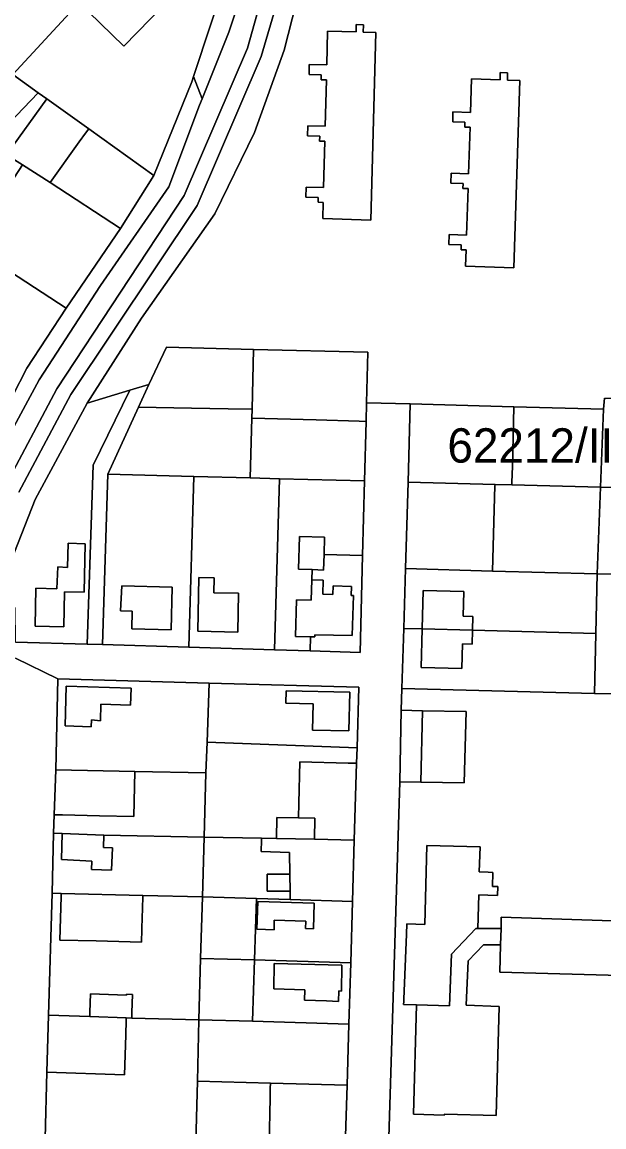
# Model space of a CAD drawing. Extents: x -502026 to -497664, y -1143484 to -1138019.
# Drawn here: x -498053.3 to -497917.6, y -1140189 to -1139931.4 of the extents above; entities that cross this region are included whole.
import ezdxf

# ---------------------------------------------------------------- set-up
doc = ezdxf.new("R2010")
doc.units = 0
for name, color, linetype in [('25', 7, 'Continuous'), ('31', 7, 'Continuous'), ('37', 7, 'Continuous'), ('43', 7, 'Continuous'), ('49', 7, 'Continuous'), ('55', 7, 'Continuous'), ('62', 7, 'Continuous'), ('7', 7, 'Continuous')]:
    doc.layers.add(name, color=color, linetype=linetype)

msp = doc.modelspace()

# ---------------------------------------------------------------- linework, layer by layer
at = {"layer": '25'}
for points in [[(-498005.22, -1139919.56), (-498013.29, -1139944.08), (-498013.7, -1139945.33), (-498022.56, -1139967.15), (-498037.76, -1139956.26), (-498047.52, -1139949.27), (-498049.52, -1139947.83), (-498055.44, -1139943.59), (-498027.12, -1139912.89)], [(-498020.21, -1139927.43), (-498028.47, -1139919.4), (-498037.8, -1139929), (-498029.54, -1139937.02)], [(-498047.52, -1139949.27), (-498056.92, -1139962.31), (-498053.17, -1139964.63), (-498065.44, -1139983.49), (-498043.03, -1139998.07), (-498052.15, -1140012.08), (-498058.96, -1140025.11), (-498063.8, -1140022.04), (-498076.32, -1140014.11), (-498093.67, -1140016.92), (-498094.53, -1140023.68), (-498095.59, -1140032.09), (-498118.27, -1140027.6), (-498121.71, -1140026.79), (-498122.55, -1140009.45), (-498079.55, -1139968), (-498078.04, -1139969.45), (-498073.93, -1139965.16), (-498069.88, -1139969.05), (-498049.52, -1139947.83)], [(-498037.76, -1139956.26), (-498038.47, -1139957.24), (-498039.95, -1139959.31), (-498046.76, -1139968.79), (-498053.17, -1139964.63), (-498056.92, -1139962.31), (-498047.52, -1139949.27)], [(-498046.76, -1139968.79), (-498030.37, -1139979.5), (-498043.03, -1139998.07), (-498065.44, -1139983.49), (-498053.17, -1139964.63)], [(-498038.09, -1140076.42), (-498054.83, -1140075.94), (-498054.88, -1140067.92), (-498059.95, -1140067.22), (-498050.2, -1140042.69), (-498038.13, -1140020.23), (-498028.18, -1140017.21), (-498036.75, -1140034.66)], [(-497999.66, -1140021.66), (-497999.71, -1140023.69), (-498000.11, -1140037.65), (-498013.26, -1140037.31), (-498033.33, -1140036.77), (-498026.13, -1140021.13), (-498013.75, -1140021.38), (-498005.23, -1140021.55)], [(-497917.72, -1140021.63), (-497918.4, -1140039.82), (-497939.09, -1140039.26), (-497939.07, -1140038.61), (-497938.97, -1140035.01), (-497938.59, -1140021.1)], [(-497973.05, -1140024.47), (-497973.42, -1140038.36), (-497993.26, -1140037.83), (-498000.11, -1140037.65), (-497999.71, -1140023.69), (-497984.71, -1140024.11), (-497974.68, -1140024.42)], [(-498013.26, -1140037.31), (-498014.44, -1140077.12), (-498034.57, -1140076.51), (-498033.33, -1140036.77)], [(-498000.11, -1140037.65), (-497993.26, -1140037.83), (-497994.45, -1140077.73), (-498014.44, -1140077.12), (-498013.26, -1140037.31)], [(-497973.42, -1140038.36), (-497973.88, -1140055.76), (-497982.88, -1140055.52), (-497982.75, -1140051.46), (-497988.62, -1140051.29), (-497988.84, -1140058.94), (-497985.67, -1140059.04), (-497985.73, -1140061.42), (-497985.85, -1140066.15), (-497989.29, -1140066.08), (-497989.52, -1140074.6), (-497986.07, -1140074.7), (-497986.15, -1140077.99), (-497994.45, -1140077.73), (-497993.26, -1140037.83)], [(-497939.09, -1140039.26), (-497918.4, -1140039.82), (-497919.2, -1140060.05), (-497943.58, -1140059.37), (-497943.18, -1140045.02), (-497943.02, -1140039.47), (-497943.01, -1140039.15)], [(-498038.56, -1140053.03), (-498042.57, -1140052.9), (-498042.73, -1140058.52), (-498044.98, -1140058.42), (-498045.21, -1140063.52), (-498050.12, -1140063.35), (-498050.27, -1140072.23), (-498043.54, -1140072.4), (-498043.37, -1140064.23), (-498038.82, -1140064.26)], [(-497943.58, -1140059.37), (-497919.2, -1140060.05), (-497919.5, -1140073.92), (-497948.27, -1140073.16), (-497948.2, -1140069.94), (-497950.46, -1140069.88), (-497950.32, -1140064.15), (-497959.77, -1140063.92), (-497959.99, -1140072.87), (-497964.3, -1140072.76), (-497963.85, -1140058.8)], [(-498002.79, -1140064.56), (-498008.56, -1140064.44), (-498008.49, -1140060.93), (-498012.05, -1140060.86), (-498012.3, -1140073.4), (-498002.97, -1140073.59)], [(-498018.3, -1140063.13), (-498030.01, -1140062.84), (-498030.31, -1140068.62), (-498027.59, -1140068.69), (-498027.7, -1140072.86), (-498018.55, -1140073.09)], [(-497959.99, -1140072.87), (-497960.21, -1140081.82), (-497950.76, -1140082.05), (-497950.62, -1140076.32), (-497948.35, -1140076.38), (-497948.27, -1140073.16), (-497919.5, -1140073.92), (-497919.78, -1140087.89), (-497964.76, -1140086.73), (-497964.3, -1140072.76)], [(-498009.63, -1140085.48), (-498010.15, -1140099.29), (-498010.42, -1140106.45), (-498027.03, -1140106.09), (-498045.43, -1140105.7), (-498044.98, -1140084.53)], [(-497975.18, -1140100.61), (-498010.15, -1140099.29), (-498009.63, -1140085.48), (-497974.76, -1140086.42)], [(-498027.85, -1140086.66), (-498043.02, -1140086.22), (-498043.23, -1140095.48), (-498037.18, -1140095.66), (-498037.11, -1140094.08), (-498035.02, -1140094.25), (-498034.91, -1140090.41), (-498028.03, -1140090.62)], [(-497976.85, -1140087.63), (-497991.72, -1140087.29), (-497991.79, -1140090.16), (-497985.44, -1140090.31), (-497985.58, -1140096.46), (-497977.06, -1140096.65)], [(-497975.18, -1140100.61), (-497975.29, -1140104.17), (-497977.24, -1140104.12), (-497988.55, -1140103.85), (-497988.78, -1140113.5), (-497988.86, -1140116.92), (-497993.85, -1140116.82), (-497993.95, -1140121.74), (-497997.45, -1140121.67), (-498010.81, -1140121.42), (-498010.42, -1140106.45), (-498010.15, -1140099.29)], [(-498010.42, -1140106.45), (-498010.81, -1140121.42), (-498034.19, -1140120.97), (-498043.93, -1140120.58), (-498045.95, -1140120.5), (-498045.8, -1140116.2), (-498043.85, -1140116.24), (-498035.25, -1140116.42), (-498027.25, -1140116.59), (-498027.03, -1140106.09)], [(-498043.93, -1140120.58), (-498044.13, -1140126.61), (-498037.03, -1140126.98), (-498037.11, -1140128.93), (-498032.41, -1140129.12), (-498032.2, -1140123.88), (-498034.3, -1140123.8), (-498034.19, -1140120.97), (-498010.81, -1140121.42), (-498011.23, -1140135.35), (-498025.15, -1140135), (-498044.18, -1140134.53), (-498046.31, -1140134.48), (-498045.95, -1140120.5)], [(-497997.45, -1140121.67), (-497997.46, -1140122.08), (-497997.56, -1140124.78), (-497990.91, -1140125.01), (-497990.85, -1140130.04), (-497996.15, -1140130.04), (-497996.15, -1140134.03), (-497990.8, -1140134.03), (-497990.78, -1140135.96), (-497998.6, -1140135.73), (-498011.23, -1140135.35), (-498010.81, -1140121.42)], [(-498044.18, -1140134.53), (-498044.2, -1140135.23), (-498044.46, -1140145.41), (-498036.05, -1140145.62), (-498025.45, -1140145.88), (-498025.29, -1140139.96), (-498025.24, -1140138.26), (-498025.15, -1140135), (-498011.23, -1140135.35), (-498011.66, -1140149.69), (-498012.08, -1140163.99), (-498027.72, -1140163.59), (-498027.68, -1140162.27), (-498027.55, -1140158.07), (-498028.95, -1140158.03), (-498028.96, -1140158.23), (-498037.35, -1140157.96), (-498037.49, -1140162.21), (-498037.52, -1140163.26), (-498047.11, -1140162.92), (-498046.31, -1140134.48)], [(-497998.6, -1140135.73), (-497999.09, -1140150.05), (-498011.66, -1140149.69), (-498011.23, -1140135.35)], [(-497999.09, -1140150.05), (-497999.58, -1140164.34), (-498012.08, -1140163.99), (-498011.66, -1140149.69)], [(-498027.72, -1140163.59), (-498012.08, -1140163.99), (-498012.35, -1140178.27), (-498012.76, -1140192.53), (-498025.24, -1140192.2), (-498047.91, -1140191.6), (-498047.48, -1140176.22), (-498029.39, -1140176.79), (-498029.1, -1140167.6), (-498028.99, -1140164.11), (-498028.98, -1140163.56)], [(-497995.39, -1140178.74), (-497995.41, -1140179.91), (-497995.45, -1140182.15), (-497995.67, -1140193.09), (-497977.93, -1140193.45), (-497978.15, -1140207.04), (-498013.02, -1140205.86), (-498012.76, -1140192.53), (-498012.35, -1140178.27)]]:
    msp.add_lwpolyline(points, close=True, dxfattribs=at)
at = {"layer": '31'}
msp.add_lwpolyline([(-497919.78, -1140087.89), (-497914.28, -1140087.97), (-497910.2, -1140087.99), (-497909.93, -1140102.1), (-497891.84, -1140102.75), (-497886.98, -1140102.93), (-497886.6, -1140093.94), (-497883.55, -1140094.07), (-497883.98, -1140104.14), (-497844.89, -1140104.71), (-497845.87, -1140137.92), (-497847.61, -1140196.96), (-497967.82, -1140193.95), (-497965.21, -1140108.5), (-497960.29, -1140108.61), (-497950.17, -1140108.76), (-497949.77, -1140092.14), (-497959.95, -1140091.98), (-497964.86, -1140091.83), (-497964.76, -1140086.73)], close=True, dxfattribs=at)
msp.add_lwpolyline([(-497910.97, -1140141.1), (-497941.61, -1140140.04), (-497941.6, -1140142.72), (-497946.98, -1140142.7), (-497946.81, -1140134.89), (-497944.72, -1140134.94), (-497942.42, -1140134.99), (-497942.37, -1140132.9), (-497943.57, -1140132.88), (-497943.49, -1140129.63), (-497944.6, -1140129.6), (-497946.69, -1140129.53), (-497946.48, -1140123.68), (-497958.94, -1140123.36), (-497959.38, -1140141.79), (-497963.56, -1140141.61), (-497963.66, -1140143.99), (-497964.27, -1140159.22), (-497964.29, -1140159.72), (-497964.32, -1140160.43), (-497961.31, -1140160.5), (-497962.04, -1140186.01), (-497954.85, -1140186.22), (-497954.81, -1140185.98), (-497942.73, -1140186.33), (-497942.07, -1140160.88), (-497949.71, -1140160.61), (-497949.28, -1140150.25), (-497945.73, -1140146.52), (-497941.7, -1140146.55), (-497941.91, -1140152.89), (-497911.05, -1140153.78)], dxfattribs=at)
at = {"layer": '37'}
msp.add_lwpolyline([(-498027.12, -1139912.89), (-498055.44, -1139943.59), (-498049.52, -1139947.83), (-498069.88, -1139969.05), (-498073.93, -1139965.16), (-498078.04, -1139969.45), (-498079.55, -1139968), (-498122.55, -1140009.45), (-498134.19, -1139993.42), (-498132.36, -1139979.34), (-498140.96, -1139969.15), (-498140.08, -1139963.56), (-498120.51, -1139961.49), (-498112.66, -1139952.19), (-498096.58, -1139946.36), (-498093.06, -1139940.14), (-498073.7, -1139934.12), (-498075.01, -1139920.31), (-498049.57, -1139915.41), (-498034.71, -1139902.25)], close=True, dxfattribs=at)
at = {"layer": '43'}
msp.add_lwpolyline([(-498000.78, -1139920.93), (-498005.08, -1139933.72), (-498011.32, -1139949.27), (-498013.29, -1139944.08), (-498005.22, -1139919.56)], dxfattribs=at)
at = {"layer": '49'}
for points in [[(-497989.72, -1139912.63), (-497997.51, -1139939.38), (-498012.5, -1139974.16), (-498041.93, -1140018.22), (-498054.05, -1140040.95)], [(-498057.39, -1140039.9), (-498045.16, -1140016.86), (-498015.53, -1139971.77), (-498000.7, -1139937.46), (-497994.32, -1139914.64)]]:
    msp.add_lwpolyline(points, dxfattribs=at)
at = {"layer": '55'}
for points in [[(-497982.83, -1139901.29), (-497992.15, -1139937.92), (-497999.1, -1139957.15), (-498008.36, -1139976.05), (-498025.48, -1140000.43), (-498038.13, -1140020.23), (-498050.2, -1140042.69), (-498059.95, -1140067.22)], [(-498054.05, -1140040.95), (-498041.93, -1140018.22), (-498012.5, -1139974.16), (-497997.51, -1139939.38), (-497989.72, -1139912.63)], [(-497994.32, -1139914.64), (-498000.7, -1139937.46), (-498015.53, -1139971.77), (-498045.16, -1140016.86), (-498057.39, -1140039.9)], [(-498061.7, -1140037.59), (-498049.31, -1140014.76), (-498035.04, -1139992.75), (-498019.07, -1139969.8), (-498011.9, -1139950.71), (-498011.32, -1139949.27), (-498005.08, -1139933.72), (-498000.78, -1139920.93)], [(-498058.96, -1140025.11), (-498052.15, -1140012.08), (-498043.03, -1139998.07), (-498030.37, -1139979.5), (-498022.56, -1139967.15), (-498013.7, -1139945.33), (-498013.29, -1139944.08), (-498011.32, -1139949.27), (-498011.9, -1139950.71), (-498019.07, -1139969.8), (-498035.04, -1139992.75), (-498049.31, -1140014.76), (-498061.7, -1140037.59)], [(-498054.83, -1140075.94), (-498038.09, -1140076.42), (-498034.57, -1140076.51), (-498014.44, -1140077.12), (-497994.45, -1140077.73), (-497986.15, -1140077.99), (-497974.47, -1140078.35), (-497973.88, -1140055.76), (-497973.42, -1140038.36), (-497973.05, -1140024.47), (-497972.94, -1140020.12), (-497962.79, -1140020.41), (-497963.26, -1140038.61), (-497963.85, -1140058.8), (-497964.3, -1140072.76), (-497964.76, -1140086.73), (-497964.86, -1140091.83), (-497965.21, -1140108.5), (-497967.82, -1140193.95)], [(-498054.82, -1140079.71), (-498044.98, -1140084.53), (-498045.43, -1140105.7), (-498045.8, -1140116.2), (-498045.95, -1140120.5), (-498046.31, -1140134.48), (-498047.11, -1140162.92), (-498047.48, -1140176.22), (-498047.91, -1140191.6), (-498048.33, -1140205.79), (-498048.75, -1140220.07), (-498049.18, -1140234.51), (-498049.6, -1140248.54), (-498050.04, -1140263.52), (-498050.48, -1140278.43), (-498050.89, -1140292.25), (-498051.72, -1140319.34), (-498061.89, -1140318.32)], [(-497977.93, -1140193.45), (-497977.51, -1140179.27), (-497977.09, -1140164.98), (-497976.66, -1140150.68), (-497976.24, -1140136.39), (-497975.82, -1140122.09), (-497975.29, -1140104.17), (-497975.18, -1140100.61), (-497974.76, -1140086.42), (-498009.63, -1140085.48), (-498044.98, -1140084.53), (-498054.82, -1140079.71)]]:
    msp.add_lwpolyline(points, dxfattribs=at)
for points in [[(-498020.21, -1139927.43), (-498029.54, -1139937.02), (-498037.8, -1139929), (-498028.47, -1139919.4)], [(-497973.68, -1139932.01), (-497973.72, -1139933.69), (-497970.82, -1139933.82), (-497971.93, -1139977.57), (-497983.18, -1139977.2), (-497983.08, -1139973.42), (-497984.28, -1139973.39), (-497984.25, -1139972.24), (-497987.12, -1139972.16), (-497987.06, -1139969.83), (-497982.99, -1139969.93), (-497982.71, -1139959.14), (-497983.91, -1139959.11), (-497983.88, -1139957.96), (-497986.75, -1139957.88), (-497986.68, -1139955.54), (-497982.62, -1139955.65), (-497982.34, -1139944.85), (-497983.54, -1139944.82), (-497983.51, -1139943.67), (-497986.37, -1139943.6), (-497986.31, -1139941.26), (-497982.25, -1139941.37), (-497982.04, -1139933.47), (-497975.4, -1139933.64), (-497975.36, -1139931.96)], [(-497940.08, -1139943.18), (-497940.11, -1139944.91), (-497937.2, -1139945.02), (-497938.59, -1139988.67), (-497949.86, -1139988.3), (-497949.74, -1139984.51), (-497950.94, -1139984.48), (-497950.91, -1139983.33), (-497953.78, -1139983.24), (-497953.7, -1139980.89), (-497949.63, -1139981.02), (-497949.29, -1139970.21), (-497950.49, -1139970.17), (-497950.46, -1139969.02), (-497953.33, -1139968.93), (-497953.26, -1139966.59), (-497949.18, -1139966.72), (-497948.84, -1139955.91), (-497950.05, -1139955.87), (-497950.01, -1139954.72), (-497952.88, -1139954.63), (-497952.81, -1139952.29), (-497948.74, -1139952.42), (-497948.49, -1139944.6), (-497941.81, -1139944.85), (-497941.78, -1139943.15)], [(-498022.56, -1139967.15), (-498030.37, -1139979.5), (-498046.76, -1139968.79), (-498039.95, -1139959.31), (-498038.47, -1139957.24), (-498037.76, -1139956.26)], [(-497999.32, -1140007.68), (-497999.66, -1140021.66), (-498005.23, -1140021.55), (-498013.75, -1140021.38), (-498026.13, -1140021.13), (-498023.7, -1140015.86), (-498019.61, -1140007.15)], [(-497972.94, -1140020.12), (-497973.05, -1140024.47), (-497974.68, -1140024.42), (-497984.71, -1140024.11), (-497999.71, -1140023.69), (-497999.66, -1140021.66), (-497999.32, -1140007.68), (-497972.63, -1140008.37)], [(-498026.13, -1140021.13), (-498033.33, -1140036.77), (-498034.57, -1140076.51), (-498038.09, -1140076.42), (-498036.75, -1140034.66), (-498028.18, -1140017.21), (-498023.7, -1140015.86)], [(-497938.59, -1140021.1), (-497938.97, -1140035.01), (-497939.07, -1140038.61), (-497939.09, -1140039.26), (-497943.01, -1140039.15), (-497963.26, -1140038.61), (-497962.79, -1140020.41)], [(-497912.35, -1140019.09), (-497912.82, -1140025.22), (-497913.06, -1140039.93), (-497918.4, -1140039.82), (-497917.72, -1140021.63), (-497917.52, -1140019.03)], [(-497943.01, -1140039.15), (-497943.02, -1140039.47), (-497943.18, -1140045.02), (-497943.58, -1140059.37), (-497963.85, -1140058.8), (-497963.26, -1140038.61)], [(-497913.06, -1140039.93), (-497913.49, -1140060.12), (-497919.2, -1140060.05), (-497918.4, -1140039.82)], [(-497982.88, -1140055.52), (-497983, -1140059.13), (-497985.67, -1140059.04), (-497988.84, -1140058.94), (-497988.62, -1140051.29), (-497982.75, -1140051.46)], [(-498038.56, -1140053.03), (-498038.82, -1140064.26), (-498043.37, -1140064.23), (-498043.54, -1140072.4), (-498050.27, -1140072.23), (-498050.12, -1140063.35), (-498045.21, -1140063.52), (-498044.98, -1140058.42), (-498042.73, -1140058.52), (-498042.57, -1140052.9)], [(-497973.88, -1140055.76), (-497974.47, -1140078.35), (-497986.15, -1140077.99), (-497986.07, -1140074.7), (-497985.02, -1140074.73), (-497985.01, -1140074.22), (-497976.35, -1140074.4), (-497975.98, -1140065.03), (-497976.56, -1140065.03), (-497976.46, -1140062.97), (-497980.76, -1140062.84), (-497980.82, -1140064.86), (-497983.14, -1140064.77), (-497983.06, -1140061.5), (-497985.73, -1140061.42), (-497985.67, -1140059.04), (-497983, -1140059.13), (-497982.88, -1140055.52)], [(-498002.79, -1140064.56), (-498002.97, -1140073.59), (-498012.3, -1140073.4), (-498012.05, -1140060.86), (-498008.49, -1140060.93), (-498008.56, -1140064.44)], [(-497986.07, -1140074.7), (-497989.52, -1140074.6), (-497989.29, -1140066.08), (-497985.85, -1140066.15), (-497985.73, -1140061.42), (-497983.06, -1140061.5), (-497983.14, -1140064.77), (-497980.82, -1140064.86), (-497980.76, -1140062.84), (-497976.46, -1140062.97), (-497976.56, -1140065.03), (-497975.98, -1140065.03), (-497976.35, -1140074.4), (-497985.01, -1140074.22), (-497985.02, -1140074.73)], [(-497913.49, -1140060.12), (-497913.85, -1140073.22), (-497913.87, -1140074), (-497914.23, -1140086.21), (-497914.28, -1140087.97), (-497919.78, -1140087.89), (-497919.5, -1140073.92), (-497919.2, -1140060.05)], [(-498018.3, -1140063.13), (-498018.55, -1140073.09), (-498027.7, -1140072.86), (-498027.59, -1140068.69), (-498030.31, -1140068.62), (-498030.01, -1140062.84)], [(-497948.27, -1140073.16), (-497959.99, -1140072.87), (-497959.77, -1140063.92), (-497950.32, -1140064.15), (-497950.46, -1140069.88), (-497948.2, -1140069.94)], [(-497948.27, -1140073.16), (-497948.35, -1140076.38), (-497950.62, -1140076.32), (-497950.76, -1140082.05), (-497960.21, -1140081.82), (-497959.99, -1140072.87)], [(-498027.85, -1140086.66), (-498028.03, -1140090.62), (-498034.91, -1140090.41), (-498035.02, -1140094.25), (-498037.11, -1140094.08), (-498037.18, -1140095.66), (-498043.23, -1140095.48), (-498043.02, -1140086.22)], [(-497976.85, -1140087.63), (-497977.06, -1140096.65), (-497985.58, -1140096.46), (-497985.44, -1140090.31), (-497991.79, -1140090.16), (-497991.72, -1140087.29)], [(-497959.95, -1140091.98), (-497960.29, -1140108.61), (-497965.21, -1140108.5), (-497964.86, -1140091.83)], [(-497960.29, -1140108.61), (-497959.95, -1140091.98), (-497949.77, -1140092.14), (-497950.17, -1140108.76)], [(-498027.03, -1140106.09), (-498027.25, -1140116.59), (-498035.25, -1140116.42), (-498043.85, -1140116.24), (-498045.8, -1140116.2), (-498045.43, -1140105.7)], [(-497975.29, -1140104.17), (-497975.82, -1140122.09), (-497985.09, -1140121.91), (-497984.99, -1140116.99), (-497988.86, -1140116.92), (-497988.78, -1140113.5), (-497988.55, -1140103.85), (-497977.24, -1140104.12)], [(-497897.35, -1140111.94), (-497897.69, -1140123.98), (-497897.66, -1140124.89), (-497900.66, -1140124.82), (-497901.19, -1140150.48), (-497897.38, -1140150.59), (-497897.42, -1140151.73), (-497896.32, -1140151.77), (-497896.53, -1140159.22), (-497907.77, -1140158.9), (-497910.71, -1140158.81), (-497911.2, -1140158.8), (-497911.05, -1140153.78), (-497941.91, -1140152.89), (-497941.7, -1140146.55), (-497941.6, -1140142.72), (-497941.61, -1140140.04), (-497910.97, -1140141.1), (-497910.88, -1140137.2), (-497913.58, -1140137.14), (-497913.54, -1140135.34), (-497910.84, -1140135.4), (-497910.28, -1140111.64)], [(-497988.86, -1140116.92), (-497984.99, -1140116.99), (-497985.09, -1140121.91), (-497993.95, -1140121.74), (-497993.85, -1140116.82)], [(-498034.19, -1140120.97), (-498034.3, -1140123.8), (-498032.2, -1140123.88), (-498032.41, -1140129.12), (-498037.11, -1140128.93), (-498037.03, -1140126.98), (-498044.13, -1140126.61), (-498043.93, -1140120.58)], [(-497993.95, -1140121.74), (-497985.09, -1140121.91), (-497975.82, -1140122.09), (-497976.24, -1140136.39), (-497990.78, -1140135.96), (-497990.8, -1140134.03), (-497990.85, -1140130.04), (-497990.91, -1140125.01), (-497997.56, -1140124.78), (-497997.46, -1140122.08), (-497997.45, -1140121.67)], [(-497946.98, -1140142.7), (-497947.47, -1140142.69), (-497953.16, -1140148.69), (-497953.62, -1140160.7), (-497961.31, -1140160.5), (-497964.32, -1140160.43), (-497964.29, -1140159.72), (-497964.27, -1140159.22), (-497963.66, -1140143.99), (-497963.56, -1140141.61), (-497959.38, -1140141.79), (-497958.94, -1140123.36), (-497946.48, -1140123.68), (-497946.69, -1140129.53), (-497944.6, -1140129.6), (-497943.49, -1140129.63), (-497943.57, -1140132.88), (-497942.37, -1140132.9), (-497942.42, -1140134.99), (-497944.72, -1140134.94), (-497946.81, -1140134.89)], [(-497990.8, -1140134.03), (-497996.15, -1140134.03), (-497996.15, -1140130.04), (-497990.85, -1140130.04)], [(-498025.15, -1140135), (-498025.24, -1140138.26), (-498025.29, -1140139.96), (-498025.45, -1140145.88), (-498036.05, -1140145.62), (-498044.46, -1140145.41), (-498044.2, -1140135.23), (-498044.18, -1140134.53)], [(-497990.78, -1140135.96), (-497976.24, -1140136.39), (-497976.66, -1140150.68), (-497999.09, -1140150.05), (-497998.6, -1140135.73)], [(-497985.2, -1140136.83), (-497998.34, -1140136.42), (-497998.54, -1140142.86), (-497994.54, -1140142.99), (-497994.47, -1140140.77), (-497987.12, -1140141), (-497987.17, -1140142.73), (-497985.34, -1140142.79)], [(-497985.2, -1140136.83), (-497985.34, -1140142.79), (-497987.17, -1140142.73), (-497987.12, -1140141), (-497994.47, -1140140.77), (-497994.54, -1140142.99), (-497998.54, -1140142.86), (-497998.34, -1140136.42)], [(-497946.98, -1140142.7), (-497941.6, -1140142.72), (-497941.7, -1140146.55), (-497945.73, -1140146.52), (-497949.28, -1140150.25), (-497949.71, -1140160.61), (-497942.07, -1140160.88), (-497942.73, -1140186.33), (-497954.81, -1140185.98), (-497954.85, -1140186.22), (-497962.04, -1140186.01), (-497961.31, -1140160.5), (-497953.62, -1140160.7), (-497953.16, -1140148.69), (-497947.47, -1140142.69)], [(-497976.66, -1140150.68), (-497977.09, -1140164.98), (-497999.58, -1140164.34), (-497999.09, -1140150.05)], [(-497978.7, -1140151.27), (-497978.82, -1140157.29), (-497979.42, -1140157.26), (-497979.47, -1140159.71), (-497982.33, -1140159.6), (-497987.45, -1140159.42), (-497987.37, -1140157), (-497994.61, -1140156.81), (-497994.53, -1140150.83)], [(-497978.7, -1140151.27), (-497994.53, -1140150.83), (-497994.61, -1140156.81), (-497987.37, -1140157), (-497987.45, -1140159.42), (-497982.33, -1140159.6), (-497979.47, -1140159.71), (-497979.42, -1140157.26), (-497978.82, -1140157.29)], [(-498027.72, -1140163.59), (-498028.98, -1140163.56), (-498037.52, -1140163.26), (-498037.49, -1140162.21), (-498037.35, -1140157.96), (-498028.96, -1140158.23), (-498028.95, -1140158.03), (-498027.55, -1140158.07), (-498027.68, -1140162.27)], [(-498037.52, -1140163.26), (-498028.98, -1140163.56), (-498028.99, -1140164.11), (-498029.1, -1140167.6), (-498029.39, -1140176.79), (-498047.48, -1140176.22), (-498047.11, -1140162.92)], [(-497999.58, -1140164.34), (-497977.09, -1140164.98), (-497977.51, -1140179.27), (-497995.39, -1140178.74), (-498012.35, -1140178.27), (-498012.08, -1140163.99)], [(-497977.51, -1140179.27), (-497977.93, -1140193.45), (-497995.67, -1140193.09), (-497995.45, -1140182.15), (-497995.41, -1140179.91), (-497995.39, -1140178.74)]]:
    msp.add_lwpolyline(points, close=True, dxfattribs=at)
at = {"layer": '7'}
msp.add_lwpolyline([(-497917.52, -1140019.03), (-497917.72, -1140021.63), (-497938.59, -1140021.1), (-497962.79, -1140020.41), (-497972.94, -1140020.12), (-497972.63, -1140008.37), (-497999.32, -1140007.68), (-498019.61, -1140007.15), (-498023.7, -1140015.86), (-498028.18, -1140017.21), (-498038.13, -1140020.23), (-498025.48, -1140000.43), (-498008.36, -1139976.05), (-497999.1, -1139957.15), (-497992.15, -1139937.92), (-497982.83, -1139901.29)], dxfattribs=at)
for points in [[(-497973.68, -1139932.01), (-497975.36, -1139931.96), (-497975.4, -1139933.64), (-497982.04, -1139933.47), (-497982.25, -1139941.37), (-497986.31, -1139941.26), (-497986.37, -1139943.6), (-497983.51, -1139943.67), (-497983.54, -1139944.82), (-497982.34, -1139944.85), (-497982.62, -1139955.65), (-497986.68, -1139955.54), (-497986.75, -1139957.88), (-497983.88, -1139957.96), (-497983.91, -1139959.11), (-497982.71, -1139959.14), (-497982.99, -1139969.93), (-497987.06, -1139969.83), (-497987.12, -1139972.16), (-497984.25, -1139972.24), (-497984.28, -1139973.39), (-497983.08, -1139973.42), (-497983.18, -1139977.2), (-497971.93, -1139977.57), (-497970.82, -1139933.82), (-497973.72, -1139933.69)], [(-497940.08, -1139943.18), (-497941.78, -1139943.15), (-497941.81, -1139944.85), (-497948.49, -1139944.6), (-497948.74, -1139952.42), (-497952.81, -1139952.29), (-497952.88, -1139954.63), (-497950.01, -1139954.72), (-497950.05, -1139955.87), (-497948.84, -1139955.91), (-497949.18, -1139966.72), (-497953.26, -1139966.59), (-497953.33, -1139968.93), (-497950.46, -1139969.02), (-497950.49, -1139970.17), (-497949.29, -1139970.21), (-497949.63, -1139981.02), (-497953.7, -1139980.89), (-497953.78, -1139983.24), (-497950.91, -1139983.33), (-497950.94, -1139984.48), (-497949.74, -1139984.51), (-497949.86, -1139988.3), (-497938.59, -1139988.67), (-497937.2, -1139945.02), (-497940.11, -1139944.91)]]:
    msp.add_lwpolyline(points, close=True, dxfattribs=at)

# ---------------------------------------------------------------- texts
at = {"layer": '62'}
msp.add_text('62212/III.', height=8, dxfattribs=at).set_placement((-497954.11, -1140034.08))

doc.saveas('drawing.dxf')
